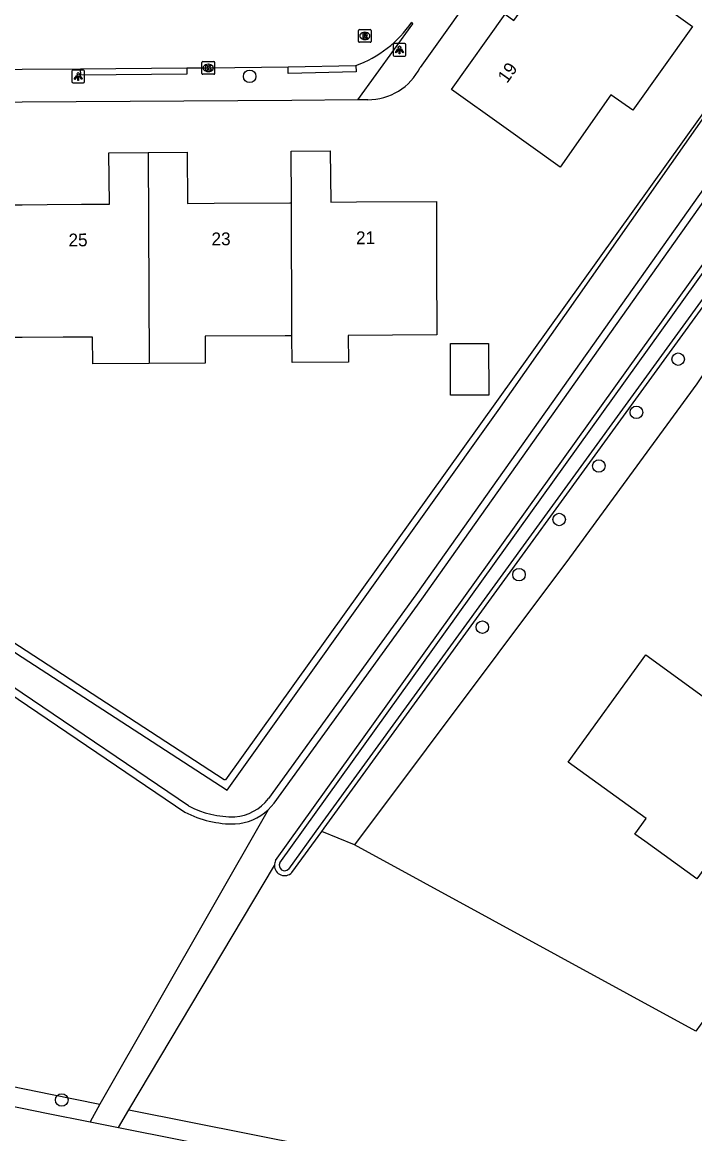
# Model space of a CAD drawing. Extents: x 157321 to 158827, y 386650 to 388532.
# Drawn here: x 158000 to 158052.4, y 387400.9 to 387487.5 of the extents above; entities that cross this region are included whole.
import ezdxf

# ---------------------------------------------------------------- set-up
doc = ezdxf.new("R2010")
doc.units = 0
for name, color, linetype in [('IMGEO_Boom', 7, 'Continuous'), ('IMGEO_Erf', 7, 'Continuous'), ('IMGEO_Fietspad_gesloten', 7, 'Continuous'), ('IMGEO_Groenvoorziening', 7, 'Continuous'), ('IMGEO_Kolk', 7, 'Continuous'), ('IMGEO_Lichtpunt', 7, 'Continuous'), ('IMGEO_Loofbos', 7, 'Continuous'), ('IMGEO_Pand', 7, 'Continuous'), ('IMGEO_Pand_nummerreeks', 7, 'Continuous'), ('IMGEO_Rijbaan_lokaal_open', 7, 'Continuous'), ('IMGEO_Rioolput', 7, 'Continuous'), ('IMGEO_Voetpad_open', 7, 'Continuous'), ('IMGEO_Waterloop', 7, 'Continuous')]:
    doc.layers.add(name, color=color, linetype=linetype)

msp = doc.modelspace()

# ---------------------------------------------------------------- linework, layer by layer
at = {"layer": 'IMGEO_Boom'}
for centre in [(158017.731, 387483.327), (158051.136, 387461.275), (158047.885, 387457.123), (158044.951, 387452.943), (158041.862, 387448.769), (158038.73, 387444.47), (158035.873, 387440.376), (158003.082, 387403.5)]:
    msp.add_circle(centre, 0.489, dxfattribs=at)
at = {"layer": 'IMGEO_Erf'}
msp.add_lwpolyline([(158077.515, 387517.338), (158077.099, 387516.491), (158075.492, 387513.532), (158066.932, 387500.229), (158056.851, 387485.731), (158015.844, 387428.477), (158015.744, 387428.46), (158000.309, 387438.514), (157984.773, 387448.624)], dxfattribs=at)
at = {"layer": 'IMGEO_Fietspad_gesloten'}
for points in [[(157965.28, 387409.942), (158000, 387402.86), (158001.904, 387402.472), (158005.292, 387401.798)], [(158005.292, 387401.798), (158007.502, 387401.358)], [(158007.502, 387401.358), (158036.519, 387395.585)]]:
    msp.add_lwpolyline(points, dxfattribs=at)
at = {"layer": 'IMGEO_Groenvoorziening'}
for points in [[(158019.757, 387422.175), (158075.515, 387500), (158080.166, 387506.154), (158081.781, 387508.524), (158084.411, 387512.927), (158086.874, 387517.425), (158087.86, 387521.456), (158089.3, 387521.319)], [(158019.172, 387426.13), (158019.638, 387426.645), (158031.142, 387442.562), (158071.593, 387499.673), (158075.686, 387505.45), (158081.435, 387515.048), (158082.741, 387517.926)], [(158023.35, 387424.434), (158023.544, 387424.701), (158078.213, 387500), (158084.169, 387508.548), (158086.353, 387512.422), (158088.747, 387517.395)], [(158068.817, 387482.359), (158060.775, 387471.746), (158052.6, 387459.356), (158042.669, 387445.775), (158025.913, 387423.407)], [(158006.052, 387403.176), (158005.292, 387401.798)], [(158007.502, 387401.358), (158008.308, 387402.727)]]:
    msp.add_lwpolyline(points, dxfattribs=at)
msp.add_arc((158020.467, 387421.789), 0.808, 151.46802, 180.99938, dxfattribs=at)
at = {"layer": 'IMGEO_Kolk'}
for p, q in [((158014.001, 387483.561), (158014.001, 387484.413)), ((158014.076, 387484.487), (158014.928, 387484.487)), ((158014.512, 387483.707), (158014.487, 387483.707)), ((158014.489, 387484.267), (158014.514, 387484.267)), ((158015.002, 387484.413), (158015.002, 387483.561)), ((158014.928, 387483.487), (158014.076, 387483.487))]:
    msp.add_line(p, q, dxfattribs=at)
for points in [[(158014.001, 387483.561), (158014.001, 387484.413)], [(158014.076, 387484.487), (158014.928, 387484.487)], [(158014.322, 387484.187), (158014.445, 387484.187), (158014.445, 387484.036), (158014.575, 387484.187), (158014.739, 387484.187), (158014.593, 387484.036), (158014.746, 387483.787), (158014.594, 387483.787), (158014.509, 387483.951), (158014.445, 387483.884), (158014.445, 387483.787), (158014.322, 387483.787), (158014.322, 387484.187)], [(158015.002, 387484.413), (158015.002, 387483.561)], [(158014.928, 387483.487), (158014.076, 387483.487)]]:
    msp.add_lwpolyline(points, dxfattribs=at)
for centre, start, end in [((158014.078, 387484.411), 91.55205, 178.44795), ((158014.078, 387484.411), 91.55205, 178.44795), ((158014.926, 387484.411), 1.55205, 88.44795), ((158014.926, 387484.411), 1.55205, 88.44795), ((158014.078, 387483.563), 181.55205, 268.44795), ((158014.078, 387483.563), 181.55205, 268.44795), ((158014.926, 387483.563), 271.55205, 358.44795), ((158014.926, 387483.563), 271.55205, 358.44795)]:
    msp.add_arc(centre, 0.0765, start, end, dxfattribs=at)
for centre, major_axis, ratio, start_param, end_param in [((158014.488, 387483.987), (-0.387, 0.002), 0.722429, 4.712389, 7.853982), ((158014.513, 387483.987), (-0.39, 0.002), 0.717154, 1.570796, 4.712389)]:
    msp.add_ellipse(centre, major_axis=major_axis, ratio=ratio, start_param=start_param, end_param=end_param, dxfattribs=at)
at = {"layer": 'IMGEO_Lichtpunt'}
for p, q in [((158028.917, 387485.799), (158028.917, 387484.992)), ((158028.917, 387485.799), (158028.917, 387484.992)), ((158029.819, 387485.894), (158029.011, 387485.894)), ((158029.819, 387485.894), (158029.011, 387485.894)), ((158029.913, 387484.992), (158029.913, 387485.799)), ((158029.913, 387484.992), (158029.913, 387485.799)), ((158029.011, 387484.898), (158029.819, 387484.898)), ((158029.011, 387484.898), (158029.819, 387484.898)), ((158003.87, 387483.721), (158003.87, 387482.914)), ((158003.87, 387483.721), (158003.87, 387482.914)), ((158004.772, 387483.816), (158003.964, 387483.816)), ((158004.772, 387483.816), (158003.964, 387483.816)), ((158004.866, 387482.914), (158004.866, 387483.721)), ((158004.866, 387482.914), (158004.866, 387483.721)), ((158003.964, 387482.82), (158004.772, 387482.82)), ((158003.964, 387482.82), (158004.772, 387482.82))]:
    msp.add_line(p, q, dxfattribs=at)
for points in [[(158029.291, 387485.463), (158029.33, 387485.435), (158029.142, 387485.173), (158029.104, 387485.2), (158029.291, 387485.463)], [(158029.503, 387485.435), (158029.541, 387485.462), (158029.728, 387485.2), (158029.689, 387485.172), (158029.503, 387485.435)], [(158029.393, 387485.415), (158029.44, 387485.415), (158029.44, 387485.093), (158029.393, 387485.093), (158029.393, 387485.415)], [(158004.244, 387483.385), (158004.283, 387483.357), (158004.095, 387483.095), (158004.057, 387483.122), (158004.244, 387483.385)], [(158004.346, 387483.337), (158004.393, 387483.337), (158004.393, 387483.015), (158004.346, 387483.015), (158004.346, 387483.337)], [(158004.456, 387483.357), (158004.494, 387483.384), (158004.681, 387483.122), (158004.642, 387483.094), (158004.456, 387483.357)]]:
    msp.add_lwpolyline(points, dxfattribs=at)
for centre in [(158029.416, 387485.597), (158004.369, 387483.519)]:
    msp.add_circle(centre, 0.0994, dxfattribs=at)
for centre, start, end in [((158029.011, 387485.799), 90, 180), ((158029.011, 387485.799), 90, 180), ((158029.819, 387485.799), 0, 90), ((158029.819, 387485.799), 0, 90), ((158029.011, 387484.992), 180, 270), ((158029.011, 387484.992), 180, 270), ((158029.819, 387484.992), 270, 0), ((158029.819, 387484.992), 270, 360), ((158003.964, 387483.721), 90, 180), ((158003.964, 387483.721), 90, 180), ((158004.772, 387483.721), 0, 90), ((158004.772, 387483.721), 0, 90), ((158003.964, 387482.914), 180, 270), ((158003.964, 387482.914), 180, 270), ((158004.772, 387482.914), 270, 0), ((158004.772, 387482.914), 270, 360)]:
    msp.add_arc(centre, 0.0946, start, end, dxfattribs=at)
at = {"layer": 'IMGEO_Loofbos'}
for points in [[(157995.977, 387437.266), (157999.682, 387434.757), (158012.685, 387425.953)], [(158019.172, 387426.13), (158006.052, 387403.176)], [(158021.029, 387421.237), (158023.35, 387424.434)], [(158025.913, 387423.407), (158023.35, 387424.434)], [(157938.986, 387423.178), (157939.492, 387422.358), (157939.912, 387421.811), (157940.464, 387421.232), (157943.532, 387418.845), (157946.758, 387416.838), (157950.186, 387415.175), (157952.604, 387414.256), (157963.557, 387411.746), (157965.56, 387411.416), (158000.3, 387404.33), (158002.2, 387403.942), (158006.052, 387403.176)], [(158053.197, 387409.793), (158052.521, 387408.871), (158025.913, 387423.407)], [(158008.308, 387402.727), (158019.659, 387421.775)], [(158008.308, 387402.727), (158036.784, 387397.062), (158042.828, 387396.157), (158047.023, 387395.909), (158056.056, 387395.411), (158059.669, 387394.897), (158063.218, 387394.006), (158064.286, 387393.615), (158066.654, 387392.749), (158069.909, 387391.154), (158070.34, 387390.911), (158074.171, 387388.791)]]:
    msp.add_lwpolyline(points, dxfattribs=at)
for centre, radius, start, end in [((158016.469, 387433.17), 8.149, 242.32775, 270.9255), ((158016.329, 387429.19), 4.177, 273.73348, 312.89481), ((158020.456, 387421.792), 0.797, 181.20768, 315.91238)]:
    msp.add_arc(centre, radius, start, end, dxfattribs=at)
at = {"layer": 'IMGEO_Pand'}
for points in [[(158040.81, 387491.131), (158041.502, 387490.636), (158043.538, 387493.483), (158047.594, 387490.575), (158052.264, 387487.227), (158047.608, 387480.682), (158045.9, 387481.886), (158041.932, 387476.257), (158037.534, 387479.397), (158033.464, 387482.303), (158037.646, 387488.168), (158038.337, 387487.673), (158040.81, 387491.131)], [(157998.663, 387473.307), (157998.836, 387473.308), (158000, 387473.317), (158001.954, 387473.332), (158004.628, 387473.353), (158006.792, 387473.37), (158006.761, 387477.373), (158009.806, 387477.399)], [(158009.806, 387477.399), (158012.857, 387477.426), (158012.889, 387473.41), (158014.963, 387473.426), (158020.851, 387473.473), (158020.992, 387473.474)], [(158009.806, 387477.399), (158009.883, 387460.926)], [(158020.992, 387473.474), (158020.979, 387477.49), (158024.02, 387477.515), (158024.047, 387473.521), (158026.064, 387473.531), (158032.289, 387473.562), (158032.302, 387468.563), (158032.317, 387463.176), (158025.412, 387463.13), (158025.426, 387461.029), (158021.033, 387461), (158021.026, 387463.1)], [(158021.026, 387463.1), (158020.992, 387473.474)], [(158009.883, 387460.926), (158005.494, 387460.896), (158005.48, 387462.995), (158003.187, 387462.98), (158000, 387462.959), (157998.87, 387462.951), (157998.714, 387462.951)], [(158021.026, 387463.1), (158020.859, 387463.099), (158020.503, 387463.097), (158014.249, 387463.054), (158014.263, 387460.955), (158009.883, 387460.926)], [(158036.362, 387462.5), (158036.373, 387458.475), (158033.401, 387458.466), (158033.39, 387462.492), (158036.362, 387462.5)], [(158057.094, 387432.051), (158061.141, 387429.114), (158059.025, 387426.192), (158057.402, 387427.36), (158056.294, 387425.851), (158052.6, 387420.747), (158048.549, 387423.678), (158047.77, 387424.24), (158048.651, 387425.458), (158042.569, 387429.855), (158048.61, 387438.21), (158057.094, 387432.051)]]:
    msp.add_lwpolyline(points, dxfattribs=at)
at = {"layer": 'IMGEO_Rijbaan_lokaal_open'}
for points in [[(157999.028, 387483.868), (158000, 387483.877), (158004.554, 387483.917)], [(158004.554, 387483.917), (158012.839, 387483.99)], [(158012.839, 387483.99), (158014.497, 387483.988), (158020.721, 387484.061)], [(158020.721, 387484.061), (158026.018, 387484.178)]]:
    msp.add_lwpolyline(points, dxfattribs=at)
msp.add_arc((158022.966, 387492.598), 8.956, 289.92506, 325.68601, dxfattribs=at)
at = {"layer": 'IMGEO_Rioolput'}
for p, q in [((158026.209, 387486.058), (158026.209, 387486.91)), ((158026.284, 387486.984), (158027.136, 387486.984)), ((158026.697, 387486.764), (158026.722, 387486.764)), ((158027.21, 387486.91), (158027.21, 387486.058)), ((158027.136, 387485.984), (158026.284, 387485.984)), ((158026.72, 387486.204), (158026.695, 387486.204))]:
    msp.add_line(p, q, dxfattribs=at)
for points in [[(158026.209, 387486.058), (158026.209, 387486.91)], [(158026.284, 387486.984), (158027.136, 387486.984)], [(158026.798, 387486.682), (158026.546, 387486.684), (158026.546, 387486.284)], [(158026.546, 387486.284), (158026.67, 387486.284), (158026.67, 387486.446), (158026.681, 387486.446)], [(158026.724, 387486.603), (158026.67, 387486.603), (158026.67, 387486.522)], [(158026.67, 387486.522), (158026.722, 387486.522)], [(158026.728, 387486.417), (158026.799, 387486.284), (158026.939, 387486.284), (158026.874, 387486.41)], [(158027.21, 387486.91), (158027.21, 387486.058)], [(158027.136, 387485.984), (158026.284, 387485.984)]]:
    msp.add_lwpolyline(points, dxfattribs=at)
for centre, radius, start, end in [((158026.286, 387486.908), 0.0765, 91.55205, 178.44795), ((158026.286, 387486.908), 0.0765, 91.55205, 178.44795), ((158026.68, 387486.393), 0.0533, 26.02933, 88.69889), ((158026.706, 387486.711), 0.19, 274.7715, 282.96867), ((158026.73, 387486.507), 0.0964, 77.00612, 93.18647), ((158026.744, 387486.564), 0.0378, 276.66336, 79.67722), ((158026.797, 387486.572), 0.109, 350.36119, 89.41601), ((158026.795, 387486.572), 0.112, 277.58423, 350.98172), ((158026.779, 387486.357), 0.108, 29.51342, 73.79051), ((158027.134, 387486.908), 0.0765, 1.55205, 88.44795), ((158027.134, 387486.908), 0.0765, 1.55205, 88.44795), ((158026.286, 387486.06), 0.0765, 181.55205, 268.44795), ((158026.286, 387486.06), 0.0765, 181.55205, 268.44795), ((158027.134, 387486.06), 0.0765, 271.55205, 358.44795), ((158027.134, 387486.06), 0.0765, 271.55205, 358.44795)]:
    msp.add_arc(centre, radius, start, end, dxfattribs=at)
for centre, major_axis, ratio, start_param, end_param in [((158026.696, 387486.484), (-0.387, 0.002), 0.722429, 4.712389, 7.853982), ((158026.721, 387486.484), (-0.39, 0.002), 0.717154, 1.570796, 4.712389)]:
    msp.add_ellipse(centre, major_axis=major_axis, ratio=ratio, start_param=start_param, end_param=end_param, dxfattribs=at)
at = {"layer": 'IMGEO_Voetpad_open'}
for points in [[(158026.142, 387481.499), (158021.016, 387481.457), (158000, 387481.305), (157990.079, 387481.233), (157962.562, 387496.218), (157955.633, 387500), (157931.114, 387513.382), (157930.704, 387563.922), (157930.223, 387563.93), (157929.973, 387592.849)], [(158041.348, 387529.418), (158041.637, 387500), (158041.647, 387498.942), (158031.019, 387484.023)], [(158030.363, 387487.549), (158030.416, 387487.431), (158026.142, 387481.499)], [(158012.839, 387483.99), (158012.843, 387483.491), (158004.558, 387483.418), (158004.554, 387483.917)], [(158026.018, 387484.178), (158026.029, 387483.679), (158020.732, 387483.562), (158020.721, 387484.061)], [(158026.935, 387481.506), (158026.142, 387481.499)]]:
    msp.add_lwpolyline(points, dxfattribs=at)
msp.add_arc((158026.938, 387486.073), 4.567, 269.96246, 333.32922, dxfattribs=at)
at = {"layer": 'IMGEO_Waterloop'}
for points in [[(158075.819, 387499.776), (158080.473, 387505.933), (158082.1, 387508.32), (158084.739, 387512.739), (158087.229, 387517.287), (158088.15, 387521.049), (158088.947, 387520.973), (158088.997, 387520.317), (158088.933, 387519.37), (158088.733, 387518.442), (158088.399, 387517.543), (158086.018, 387512.597), (158083.849, 387508.749), (158077.905, 387500.219), (158023.238, 387424.923), (158020.748, 387421.494)], [(158082.211, 387518.128), (158080.933, 387515.311), (158075.211, 387505.76), (158071.131, 387500), (158030.681, 387442.892), (158019.197, 387427.002)], [(157985.009, 387447.804), (158000, 387438.039), (158015.967, 387427.67), (158037.115, 387457.277), (158067.056, 387500), (158072.966, 387508.665), (158077.877, 387516.888)], [(158020.087, 387421.986), (158075.819, 387499.776)], [(158012.964, 387426.448), (158000, 387435.226), (157996.276, 387437.747)]]:
    msp.add_lwpolyline(points, dxfattribs=at)
for centre, radius, start, end in [((158016.332, 387429.183), 3.601, 273.7585, 322.72078), ((158016.361, 387432.72), 7.133, 241.55651, 271.66136), ((158020.455, 387421.791), 0.417, 152.08461, 314.59279)]:
    msp.add_arc(centre, radius, start, end, dxfattribs=at)

# ---------------------------------------------------------------- texts
at = {"layer": 'IMGEO_Pand_nummerreeks'}
for s, rotation, p in [('19', 54.50948, (158037.799, 387482.732)), ('25', 0.43545, (158003.61, 387470.064)), ('23', 0.43545, (158014.761, 387470.149)), ('21', 0.43545, (158026.025, 387470.235))]:
    msp.add_text(s, height=1, rotation=rotation, dxfattribs=at).set_placement(p)

doc.saveas('drawing.dxf')
